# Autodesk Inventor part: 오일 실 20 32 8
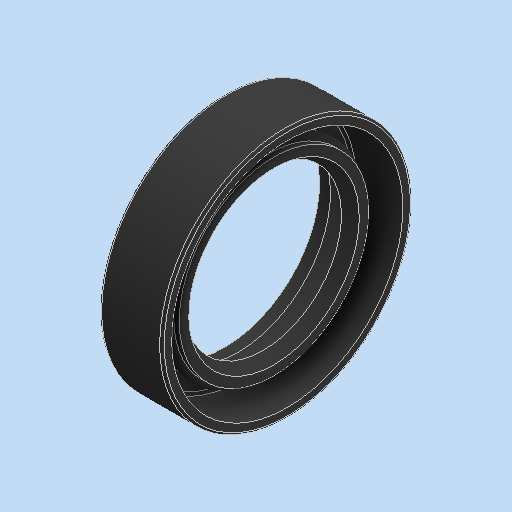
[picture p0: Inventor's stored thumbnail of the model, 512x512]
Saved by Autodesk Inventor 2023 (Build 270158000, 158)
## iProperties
Created: 2024-11
Part Number: 오일 실 20 32 8
Material: 고무
Description: 오일-실
Document SubType Name: Modeling
Designer: asung
Density: 0.93 g/cm^3
Appearance: 기본값
Author: jhkim
Sending System: Autodesk Inventor 2025
Preprocessor: ST-DEVELOPER v20
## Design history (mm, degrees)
node "오일 실 20 32 81"
node "솔리드1"
body "Solid1"
